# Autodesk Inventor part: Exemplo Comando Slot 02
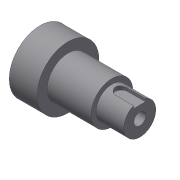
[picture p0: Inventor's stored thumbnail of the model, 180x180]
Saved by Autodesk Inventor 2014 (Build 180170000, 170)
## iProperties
Created: 2012-12
Part Number: Exemplo Comando Slot 02
Material: Genérico
Document SubType Name: Modeling
Designer: Daniel Severino
Density: 1 g/cm^3
Appearance: Default
Author: Daniel Severino
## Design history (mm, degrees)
sketch "Esboço1"
  geometry: L1 (0, 0)-(100, 0); L2 (100, 0)-(100, 10); L3 (100, 10)-(72, 10); L4 (72, 10)-(72, 15); L5 (72, 15)-(28, 15); L6 (28, 15)-(28, 25); L7 (28, 25)-(0, 25); L8 (0, 25)-(0, 0); L9 (0, -6)-(100, -6)
  constraints: 18 end point, 2 vertical, 1 horizontal
  dimensions: "d0" = 100 distance of L1.start L1.end; "d1" = 10 distance of L1.end L2.end; "d2" = 25 distance of L7.end L1.start; "d4" = 15 distance between parallel lines of L1 L5; "d5" = 28 distance of L6.end L7.end; "d9" = 28 distance of L2.end L3.end; "d10" = 6 distance between parallel lines of L9 L1
revolve "Revolução1" sketch "Esboço1" stored, may be unused: angle "d8" = 180 deg
sketch "Esboço2"
  geometry: C1 r 12.5 at (0, 0); 2 further points
  constraints: 1 centre point, 1 coincident, 1 vertical alignment
  dimensions: "d11" = 25 diameter of C1
extrude "Extrusão1" cut sketch "Esboço2" distance "d13" = 12; taper "d14" = 0 deg
workplane "Work Plane1"
sketch "Sketch3"
  geometry: L1 (-3.977, -0.482)-(26.023, -0.482); L2 (-3.977, -6.482)-(26.023, -6.482); L3 (26.023, 5.518)-(-3.977, 5.518); A1 r 6 centre (-3.977, -0.482) between (-3.977, 5.518) and (-3.977, -6.482); A2 r 6 centre (26.023, -0.482) between (26.023, -6.482) and (26.023, 5.518); 2 further points
  constraints: 8 end point, 4 point on circle, 4 tangent, 2 centre point, 1 horizontal, 1 midpoint, 1 parallel
  dimensions: "d15" = 30 distance of L2.start L2.end; "d16" = 6 radius of A2
extrude "Extrusion2" cut sketch "Sketch3" distance "d17" = 4; taper "d18" = 0 deg
node "Sólido1"
